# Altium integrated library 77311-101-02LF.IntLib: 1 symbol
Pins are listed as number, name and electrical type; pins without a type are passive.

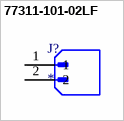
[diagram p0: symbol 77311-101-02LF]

## 77311-101-02LF
designator J?
CONN HEADER VERT 2POS 2.54MM; MF: Amphenol ICC (FCI); MP: 77311-101-02LF
footprint AMPHENOL_77311-101-02LF
pins: 1, 2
